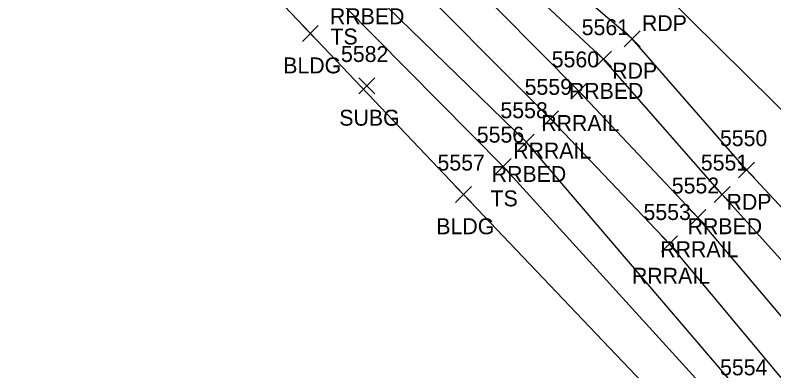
# Model space of a CAD drawing. Extents: x 1618146 to 1620418, y 640749 to 641927.
# Drawn here: x 1620082.5 to 1620177.9, y 641136.7 to 641181.4 of the extents above; entities that cross this region are included whole.
import ezdxf

# ---------------------------------------------------------------- set-up
doc = ezdxf.new("R2010")
doc.units = 0
for name, color, linetype in [('L_A', 7, 'Continuous'), ('L_I', 7, 'Continuous'), ('L_TIC', 7, 'Continuous'), ('LBC', 7, 'Continuous'), ('LELB', 7, 'Continuous'), ('P_A', 7, 'Continuous'), ('P_I', 7, 'Continuous'), ('P_TIC', 7, 'Continuous'), ('PET', 7, 'Continuous'), ('R_A', 7, 'Continuous'), ('R_I', 7, 'Continuous'), ('R_TIC', 7, 'Continuous'), ('RR', 7, 'Continuous'), ('RRB', 7, 'Continuous'), ('U_A', 7, 'Continuous'), ('U_I', 7, 'Continuous'), ('U_TIC', 7, 'Continuous')]:
    doc.layers.add(name, color=color, linetype=linetype)

msp = doc.modelspace()

# ---------------------------------------------------------------- linework, layer by layer
at = {"layer": 'L_TIC'}
for points in [[(1620118.634, 641178.081), (1620120.634, 641180.081)], [(1620120.634, 641178.081), (1620118.634, 641180.081)], [(1620142.867, 641161.38), (1620144.867, 641163.38)], [(1620144.867, 641161.38), (1620142.867, 641163.38)], [(1620137.873, 641157.876), (1620139.873, 641159.876)], [(1620139.873, 641157.876), (1620137.873, 641159.876)]]:
    msp.add_lwpolyline(points, dxfattribs=at)
at = {"layer": 'LBC'}
msp.add_lwpolyline([(1620182.251, 641113.365), (1620138.873, 641158.876), (1620119.634, 641179.081), (1620099.137, 641200.676), (1620061.444, 641164.754), (1620044.431, 641182.84), (1620044.169, 641182.771), (1620022.603, 641162.294), (1620014.935, 641155.186), (1620024.72, 641144.878), (1620017.727, 641138.107), (1620002.991, 641123.903), (1620002.581, 641122.317), (1620005.727, 641115.216)], dxfattribs=at)
at = {"layer": 'LELB'}
msp.add_lwpolyline([(1620198.161, 641096.651), (1620186.457, 641115.205), (1620172.223, 641131.175), (1620143.867, 641162.38), (1620123.748, 641182.705), (1620104.934, 641199.85), (1620097.932, 641205.844), (1620094.188, 641209.351)], dxfattribs=at)
at = {"layer": 'P_TIC'}
for points in [[(1620159.08, 641177.417), (1620161.08, 641179.417)], [(1620161.08, 641177.417), (1620159.08, 641179.417)], [(1620173.447, 641160.945), (1620175.447, 641162.945)], [(1620175.447, 641160.945), (1620173.447, 641162.945)]]:
    msp.add_lwpolyline(points, dxfattribs=at)
at = {"layer": 'PET'}
for points in [[(1620248.37, 641210.419), (1620247.05, 641196.867), (1620244.221, 641193.357), (1620231.184, 641173.763), (1620213.381, 641155.488), (1620202.395, 641145.525), (1620184.689, 641164.4), (1620181.462, 641166.888), (1620163.819, 641184.387), (1620152.297, 641193.8)], [(1620199.84, 641100.892), (1620190.476, 641119.747), (1620190.752, 641121.585), (1620192.149, 641127.788), (1620193.459, 641134.423), (1620190.666, 641144.593), (1620174.447, 641161.945), (1620160.08, 641178.417), (1620147.247, 641189.39)]]:
    msp.add_lwpolyline(points, dxfattribs=at)
at = {"layer": 'R_TIC'}
for points in [[(1620155.473, 641174.88), (1620157.473, 641176.88)], [(1620157.473, 641174.88), (1620155.473, 641176.88)], [(1620152.359, 641170.838), (1620154.359, 641172.838)], [(1620154.359, 641170.838), (1620152.359, 641172.838)], [(1620148.827, 641167.387), (1620150.827, 641169.387)], [(1620150.827, 641167.387), (1620148.827, 641169.387)], [(1620145.778, 641164.447), (1620147.778, 641166.447)], [(1620147.778, 641164.447), (1620145.778, 641166.447)], [(1620170.398, 641157.878), (1620172.398, 641159.878)], [(1620172.398, 641157.878), (1620170.398, 641159.878)], [(1620167.312, 641154.994), (1620169.312, 641156.994)], [(1620169.312, 641154.994), (1620167.312, 641156.994)], [(1620163.758, 641151.663), (1620165.758, 641153.663)], [(1620165.758, 641151.663), (1620163.758, 641153.663)]]:
    msp.add_lwpolyline(points, dxfattribs=at)
at = {"layer": 'RR'}
for points in [[(1620192.149, 641127.788), (1620168.312, 641155.994), (1620153.359, 641171.838), (1620133.437, 641191.994), (1620110.111, 641213.081), (1620101.472, 641220.641), (1620055.356, 641258.678), (1620021.942, 641286.099), (1619984.199, 641317.184), (1619946.809, 641347.804), (1619927.299, 641363.881), (1619890.892, 641393.618), (1619862.546, 641416.891)], [(1620190.752, 641121.585), (1620164.758, 641152.663), (1620149.827, 641168.387), (1620129.761, 641188.505), (1620106.878, 641209.401), (1620098.404, 641216.876), (1620053.4, 641253.963), (1620018.83, 641282.236), (1619980.557, 641313.635), (1619944.224, 641343.671), (1619924.209, 641360.052), (1619888.22, 641389.605), (1619859.159, 641413.425)]]:
    msp.add_lwpolyline(points, dxfattribs=at)
at = {"layer": 'RRB'}
for points in [[(1620282.833, 641005.905), (1620262.956, 641036.105), (1620245.554, 641062.879), (1620222.8, 641095.958), (1620205.802, 641118.707), (1620193.459, 641134.423), (1620171.398, 641158.878), (1620156.473, 641175.88), (1620136.028, 641194.899), (1620112.946, 641215.974), (1620104.578, 641223.126), (1620095.968, 641212.166)], [(1620271.861, 640991.557), (1620248.91, 641026.87), (1620231.317, 641051.296), (1620208.546, 641087.677), (1620199.84, 641100.892), (1620189.043, 641115.525), (1620174.379, 641133.159), (1620146.778, 641165.447), (1620126.451, 641185.248), (1620103.318, 641205.304), (1620095.968, 641212.166)]]:
    msp.add_lwpolyline(points, dxfattribs=at)
at = {"layer": 'U_TIC'}
for points in [[(1620125.742, 641171.51), (1620127.742, 641173.51)], [(1620127.742, 641171.51), (1620125.742, 641173.51)]]:
    msp.add_lwpolyline(points, dxfattribs=at)

# ---------------------------------------------------------------- texts
at = {"layer": 'L_A'}
for s, p in [('TS', (1620122.158, 641177.705)), ('BLDG', (1620116.224, 641174.081)), ('TS', (1620142.277, 641157.38)), ('BLDG', (1620135.464, 641153.876))]:
    msp.add_text(s, height=2, dxfattribs=at).set_placement(p)
at = {"layer": 'L_I'}
for s, p in [('5556', (1620140.552, 641165.38)), ('5557', (1620135.614, 641161.876))]:
    msp.add_text(s, height=2, dxfattribs=at).set_placement(p)
at = {"layer": 'P_A'}
for p in [(1620161.307, 641179.387), (1620157.568, 641173.417), (1620171.935, 641156.945)]:
    msp.add_text('RDP', height=2, dxfattribs=at).set_placement(p)
at = {"layer": 'P_I'}
msp.add_text('5550', height=2, dxfattribs=at).set_placement((1620171.101, 641164.945))
at = {"layer": 'R_A'}
for s, p in [('RRBED', (1620122.097, 641180.248)), ('RRBED', (1620152.119, 641170.88)), ('RRRAIL', (1620148.65, 641166.838)), ('RRRAIL', (1620145.119, 641163.387)), ('RRBED', (1620142.424, 641160.447)), ('RRBED', (1620167.043, 641153.878)), ('RRRAIL', (1620163.604, 641150.994)), ('RRRAIL', (1620160.049, 641147.663))]:
    msp.add_text(s, height=2, dxfattribs=at).set_placement(p)
at = {"layer": 'R_I'}
for s, p in [('5561', (1620153.733, 641178.88)), ('5560', (1620149.965, 641174.838)), ('5559', (1620146.56, 641171.387)), ('5558', (1620143.518, 641168.447)), ('5551', (1620168.705, 641161.878)), ('5552', (1620165.052, 641158.994)), ('5553', (1620161.498, 641155.663)), ('5554', (1620171.119, 641136.159))]:
    msp.add_text(s, height=2, dxfattribs=at).set_placement(p)
at = {"layer": 'U_A'}
msp.add_text('SUBG', height=2, dxfattribs=at).set_placement((1620123.269, 641167.51))
at = {"layer": 'U_I'}
msp.add_text('5582', height=2, dxfattribs=at).set_placement((1620123.482, 641175.51))

doc.saveas('drawing.dxf')
